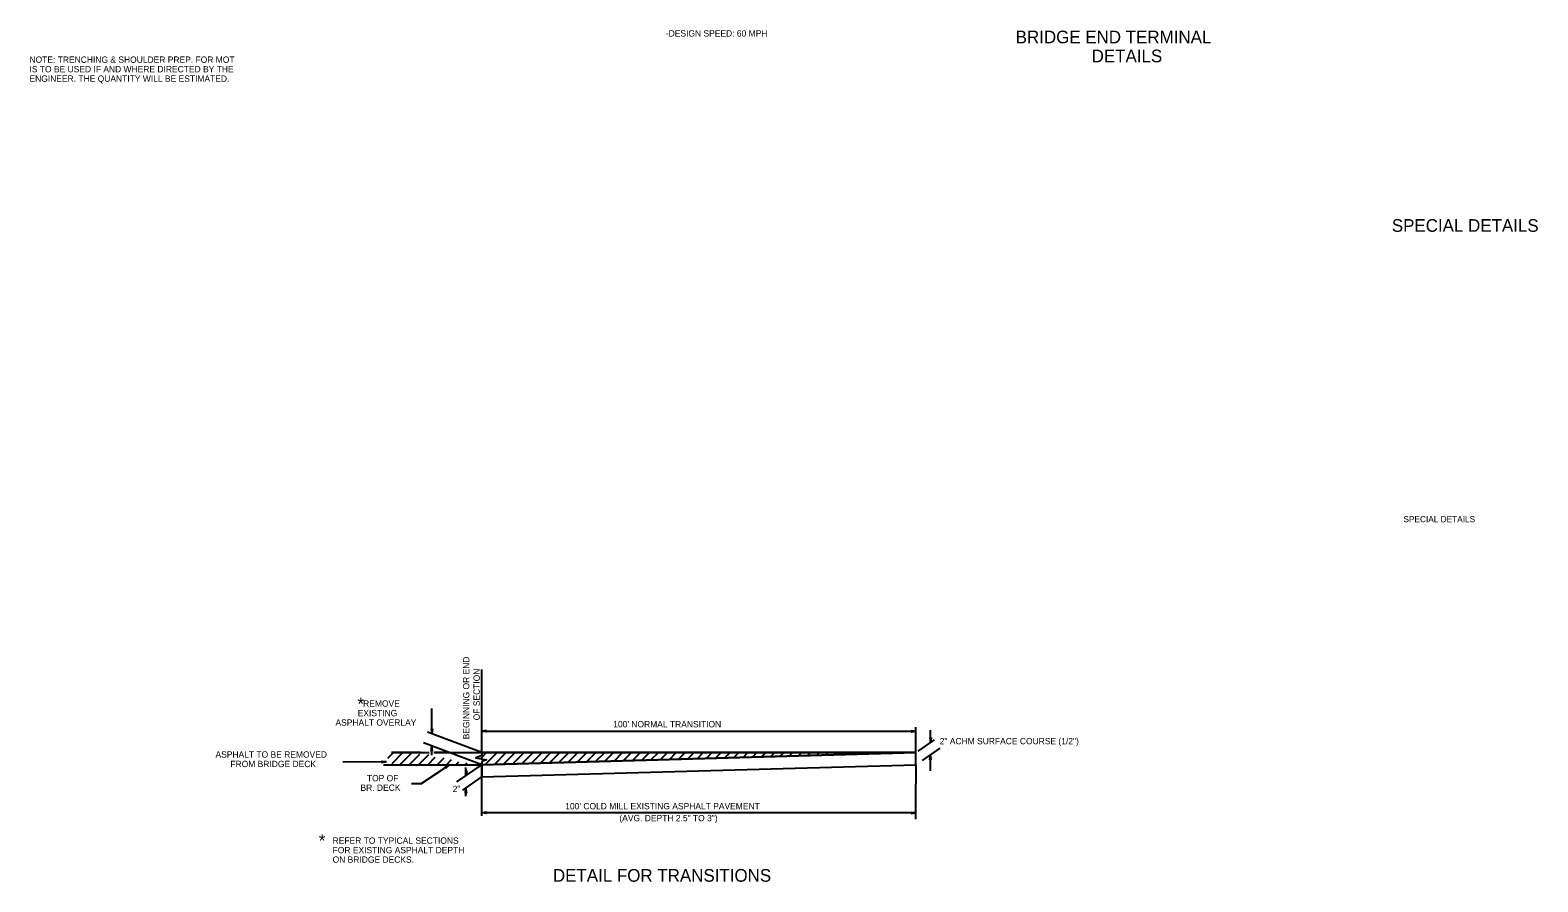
# Model space of a CAD drawing. Extents: x 1929624 to 1936506, y 596315 to 605721.
# Drawn here: x 1933916 to 1935345, y 602704 to 603512 of the extents above; entities that cross this region are included whole.
import ezdxf

# ---------------------------------------------------------------- set-up
doc = ezdxf.new("R2010")
doc.units = 0
for name, color, linetype in [('Default', 7, 'Continuous'), ('R_Border', 7, 'Continuous'), ('R_Border Prem', 7, 'Continuous')]:
    doc.layers.add(name, color=color, linetype=linetype)

msp = doc.modelspace()

# ---------------------------------------------------------------- linework, layer by layer
at = {"layer": 'Default'}
for p, q in [((1934343.8, 602827), (1934343.8, 602905.3)), ((1934296.4, 602844.5), (1934296.4, 602868.4)), ((1934343.8, 602826.5), (1934292.2, 602845.8)), ((1934295.7, 602848.9), (1934296.4, 602844.5)), ((1934295.7, 602848.9), (1934296.4, 602845.1)), ((1934297.1, 602848.9), (1934295.7, 602848.9)), ((1934296, 602848.9), (1934296.4, 602846)), ((1934296, 602848.9), (1934296.4, 602846.7)), ((1934296.2, 602848.9), (1934296.4, 602847.6)), ((1934296.2, 602848.9), (1934296.4, 602848.2)), ((1934297.1, 602848.9), (1934296.4, 602844.5)), ((1934296.6, 602848.9), (1934296.4, 602847.6)), ((1934296.8, 602848.9), (1934296.4, 602846)), ((1934296.8, 602848.9), (1934296.4, 602845.1)), ((1934296.6, 602848.9), (1934296.4, 602846.7)), ((1934296.4, 602848.9), (1934296.4, 602848.2)), ((1934348.4, 602847.4), (1934343.8, 602846.7)), ((1934343.8, 602846.7), (1934755.3, 602846.7)), ((1934348.4, 602846.1), (1934343.8, 602846.7)), ((1934348.4, 602847.2), (1934344.5, 602846.7)), ((1934348.4, 602846.1), (1934344.5, 602846.7)), ((1934348.4, 602847.2), (1934345.3, 602846.7)), ((1934348.4, 602846.3), (1934345.3, 602846.7)), ((1934348.4, 602847), (1934346.2, 602846.7)), ((1934348.4, 602846.3), (1934346.2, 602846.7)), ((1934348.4, 602847), (1934346.9, 602846.7)), ((1934348.4, 602846.5), (1934346.9, 602846.7)), ((1934348.4, 602846.7), (1934347.8, 602846.7)), ((1934348.4, 602846.5), (1934347.8, 602846.7)), ((1934348.4, 602846.1), (1934348.4, 602847.4)), ((1934750.7, 602847.4), (1934755.3, 602846.7)), ((1934750.7, 602847.4), (1934750.7, 602846.1)), ((1934750.7, 602847.2), (1934753.8, 602846.7)), ((1934750.7, 602847.2), (1934754.4, 602846.7)), ((1934750.7, 602847), (1934752.2, 602846.7)), ((1934750.7, 602847), (1934752.9, 602846.7)), ((1934750.7, 602846.1), (1934755.3, 602846.7)), ((1934750.7, 602846.5), (1934752.2, 602846.7)), ((1934750.7, 602846.3), (1934753.8, 602846.7)), ((1934750.7, 602846.1), (1934754.4, 602846.7)), ((1934750.7, 602846.3), (1934752.9, 602846.7)), ((1934750.7, 602846.5), (1934751.3, 602846.7)), ((1934750.7, 602846.7), (1934751.3, 602846.7)), ((1934755.3, 602826.5), (1934755.3, 602850.7)), ((1934769.1, 602836.1), (1934769.1, 602847.8)), ((1934343.8, 602815), (1934288.4, 602835.7)), ((1934295.7, 602828), (1934296.4, 602832.7)), ((1934295.7, 602828), (1934296.4, 602832)), ((1934296, 602828), (1934296.4, 602831.1)), ((1934296, 602828), (1934296.4, 602830.4)), ((1934296.2, 602828), (1934296.4, 602829.6)), ((1934296.2, 602828), (1934296.4, 602828.7)), ((1934297.1, 602828), (1934296.4, 602832.7)), ((1934296.4, 602824.2), (1934296.4, 602832.7)), ((1934296.8, 602828), (1934296.4, 602832)), ((1934296.8, 602828), (1934296.4, 602831.1)), ((1934296.6, 602828), (1934296.4, 602830.4)), ((1934296.6, 602828), (1934296.4, 602829.6)), ((1934296.4, 602828), (1934296.4, 602828.7)), ((1934757.4, 602828), (1934772.7, 602838.5)), ((1934761.5, 602819.1), (1934778.1, 602830.8)), ((1934768.4, 602840.7), (1934769.1, 602836.1)), ((1934769.8, 602840.7), (1934768.4, 602840.7)), ((1934768.7, 602840.7), (1934769.1, 602837.6)), ((1934768.7, 602840.7), (1934769.1, 602836.9)), ((1934768.9, 602840.7), (1934769.1, 602839.2)), ((1934768.9, 602840.7), (1934769.1, 602838.5)), ((1934769.8, 602840.7), (1934769.1, 602836.1)), ((1934769.3, 602840.7), (1934769.1, 602839.2)), ((1934769.6, 602840.7), (1934769.1, 602837.6)), ((1934769.8, 602840.7), (1934769.1, 602836.9)), ((1934769.6, 602840.7), (1934769.1, 602838.5)), ((1934769.1, 602840.7), (1934769.1, 602840.1)), ((1934769.3, 602840.7), (1934769.1, 602840.1)), ((1934212, 602817.7), (1934253.4, 602817.9)), ((1934248.7, 602817.1), (1934248.8, 602818.5)), ((1934248.7, 602818.2), (1934251.8, 602817.8)), ((1934248.7, 602817.1), (1934253.4, 602817.9)), ((1934248.8, 602818.5), (1934253.4, 602817.9)), ((1934248.8, 602818.1), (1934250.4, 602817.8)), ((1934248.8, 602818.1), (1934251, 602817.7)), ((1934248.8, 602817.4), (1934250.4, 602817.8)), ((1934248.8, 602817.8), (1934249.6, 602817.8)), ((1934248.8, 602817.8), (1934249.6, 602817.8)), ((1934248.8, 602817.4), (1934251, 602817.7)), ((1934248.9, 602818.4), (1934252.6, 602817.8)), ((1934248.9, 602817.3), (1934251.8, 602817.8)), ((1934248.9, 602817.3), (1934252.6, 602817.8)), ((1934250.5, 602815), (1934343.8, 602815)), ((1934254.8, 602821.2), (1934260, 602826.5)), ((1934258.3, 602826.5), (1934294, 602826.5)), ((1934258.7, 602816.3), (1934268.9, 602826.5)), ((1934266.7, 602815.5), (1934277.7, 602826.5)), ((1934275, 602815), (1934285, 602825)), ((1934283.9, 602815), (1934293.5, 602824.6)), ((1934286.1, 602796.9), (1934313.3, 602815)), ((1934292.7, 602815), (1934299.7, 602822)), ((1934295.7, 602828), (1934297.1, 602828)), ((1934298.2, 602826.5), (1934755.3, 602826.5)), ((1934301.5, 602815), (1934308, 602821.5)), ((1934309, 602813), (1934313.3, 602815)), ((1934309.2, 602812.9), (1934312.7, 602814.5)), ((1934309.8, 602811.8), (1934313.3, 602815)), ((1934309.9, 602812), (1934312.7, 602814.5)), ((1934310.4, 602815), (1934315.2, 602819.8)), ((1934319.2, 602815), (1934322, 602817.7)), ((1934320.2, 602798.7), (1934343.8, 602815)), ((1934328.1, 602815), (1934329.8, 602816.7)), ((1934336.9, 602815), (1934337.3, 602815.3)), ((1934342.8, 602820.8), (1934348.4, 602826.5)), ((1934343.8, 602815), (1934755.3, 602826.5)), ((1934343.8, 602766.4), (1934343.8, 602816.7)), ((1934343.8, 602803.4), (1934755.3, 602815)), ((1934355.7, 602815.3), (1934366.9, 602826.5)), ((1934755.3, 602815), (1934755.1, 602796.7)), ((1934755.3, 602815), (1934755.3, 602826.5)), ((1934768.5, 602819.6), (1934769.1, 602824.3)), ((1934768.5, 602819.6), (1934769.8, 602819.6)), ((1934768.7, 602819.6), (1934769.1, 602823.7)), ((1934768.7, 602819.6), (1934769.1, 602822.8)), ((1934768.9, 602819.6), (1934769.1, 602822.1)), ((1934768.9, 602819.6), (1934769.1, 602821.2)), ((1934769.1, 602809.2), (1934769.1, 602824.3)), ((1934769.8, 602819.6), (1934769.1, 602824.3)), ((1934769.8, 602819.6), (1934769.1, 602823.7)), ((1934769.6, 602819.6), (1934769.1, 602822.8)), ((1934769.6, 602819.6), (1934769.1, 602822.1)), ((1934769.3, 602819.6), (1934769.1, 602821.2)), ((1934769.3, 602819.6), (1934769.1, 602820.5)), ((1934769.1, 602819.6), (1934769.1, 602820.5)), ((1934309.8, 602811.8), (1934309, 602813)), ((1934309.2, 602812.7), (1934312, 602814)), ((1934309.4, 602812.6), (1934311.4, 602813.6)), ((1934309.4, 602812.6), (1934310.8, 602813.3)), ((1934309.5, 602812.4), (1934310.2, 602812.8)), ((1934309.5, 602812.4), (1934310.2, 602812.8)), ((1934309.7, 602812.1), (1934311.4, 602813.6)), ((1934309.7, 602812.1), (1934310.8, 602813.3)), ((1934309.9, 602812), (1934312, 602814)), ((1934325.8, 602790.8), (1934343.8, 602803.4)), ((1934328.2, 602809.3), (1934328.8, 602804.6)), ((1934329.5, 602809.3), (1934328.2, 602809.3)), ((1934328.4, 602809.3), (1934328.8, 602806.2)), ((1934328.4, 602809.3), (1934328.8, 602805.5)), ((1934328.6, 602809.3), (1934328.8, 602807.7)), ((1934328.6, 602809.3), (1934328.8, 602807.1)), ((1934328.8, 602804.6), (1934328.8, 602812.2)), ((1934329.5, 602809.3), (1934328.8, 602804.6)), ((1934329.1, 602809.3), (1934328.8, 602807.7)), ((1934329.3, 602809.3), (1934328.8, 602806.2)), ((1934329.5, 602809.3), (1934328.8, 602805.5)), ((1934329.3, 602809.3), (1934328.8, 602807.1)), ((1934328.8, 602809.3), (1934328.8, 602808.6)), ((1934329.1, 602809.3), (1934328.8, 602808.6)), ((1934286.1, 602796.9), (1934277.3, 602796.9)), ((1934328.2, 602788.1), (1934328.8, 602792.8)), ((1934328.2, 602788.1), (1934329.5, 602788.1)), ((1934328.4, 602788.1), (1934328.8, 602792.1)), ((1934328.4, 602788.1), (1934328.8, 602791.2)), ((1934328.6, 602788.1), (1934328.8, 602790.6)), ((1934328.6, 602788.1), (1934328.8, 602789.7)), ((1934329.5, 602788.1), (1934328.8, 602792.8)), ((1934328.8, 602785.3), (1934328.8, 602792.8)), ((1934329.5, 602788.1), (1934328.8, 602792.1)), ((1934329.3, 602788.1), (1934328.8, 602791.2)), ((1934329.3, 602788.1), (1934328.8, 602790.6)), ((1934329, 602788.1), (1934328.8, 602789.7)), ((1934329, 602788.1), (1934328.8, 602789)), ((1934328.8, 602788.1), (1934328.8, 602789)), ((1934755.1, 602763.2), (1934755.1, 602796.7)), ((1934348.2, 602769.9), (1934343.8, 602769.2)), ((1934755.1, 602769.2), (1934343.8, 602769.2)), ((1934348.2, 602768.6), (1934343.8, 602769.2)), ((1934348.2, 602769.9), (1934344.5, 602769.2)), ((1934348.2, 602768.8), (1934344.5, 602769.2)), ((1934348.2, 602769.7), (1934345.3, 602769.2)), ((1934348.2, 602768.8), (1934345.3, 602769.2)), ((1934348.2, 602769.7), (1934346, 602769.2)), ((1934348.2, 602769), (1934346, 602769.2)), ((1934348.2, 602769.4), (1934346.9, 602769.2)), ((1934348.2, 602769), (1934346.9, 602769.2)), ((1934348.2, 602769.4), (1934347.6, 602769.2)), ((1934348.2, 602769.2), (1934347.6, 602769.2)), ((1934348.2, 602768.6), (1934348.2, 602769.9)), ((1934750.7, 602769.9), (1934755.1, 602769.2)), ((1934750.7, 602769.9), (1934754.4, 602769.2)), ((1934750.7, 602769.9), (1934750.7, 602768.6)), ((1934750.7, 602769.7), (1934753.6, 602769.2)), ((1934750.7, 602769.7), (1934752.9, 602769.2)), ((1934750.7, 602769.4), (1934752, 602769.2)), ((1934750.7, 602769.4), (1934751.3, 602769.2)), ((1934750.7, 602768.6), (1934755.1, 602769.2)), ((1934750.7, 602769), (1934752, 602769.2)), ((1934750.7, 602768.8), (1934753.6, 602769.2)), ((1934750.7, 602768.8), (1934754.4, 602769.2)), ((1934750.7, 602769), (1934752.9, 602769.2)), ((1934750.7, 602769.2), (1934751.3, 602769.2))]:
    msp.add_line(p, q, dxfattribs=at)
for points in [[(1934285.6, 602826.5), (1934258.3, 602826.5)], [(1934343.8, 602815), (1934312.9, 602826.5), (1934299.2, 602826.5)], [(1934343.8, 602823.8), (1934338.1, 602821.6), (1934348.4, 602819.7), (1934343.8, 602818)], [(1934343.8, 602815), (1934343.8, 602803.4), (1934755.3, 602815), (1934755.3, 602826.5), (1934343.8, 602815)], [(1934343.8, 602815), (1934343.8, 602803.4), (1934755.3, 602815), (1934755.3, 602826.5), (1934343.8, 602815)]]:
    msp.add_lwpolyline(points, dxfattribs=at)
at = {"layer": 'R_Border'}
for p, q in [((1934347, 602815.1), (1934358.4, 602826.5)), ((1934364.4, 602815.6), (1934375.4, 602826.5)), ((1934373.2, 602815.8), (1934383.9, 602826.5)), ((1934381.9, 602816.1), (1934392.4, 602826.5)), ((1934390.6, 602816.3), (1934400.9, 602826.5)), ((1934399.4, 602816.5), (1934409.3, 602826.5)), ((1934408.1, 602816.8), (1934417.8, 602826.5)), ((1934416.8, 602817), (1934426.3, 602826.5)), ((1934425.6, 602817.3), (1934434.8, 602826.5)), ((1934434.3, 602817.5), (1934443.3, 602826.5)), ((1934443, 602817.8), (1934451.8, 602826.5)), ((1934451.7, 602818), (1934460.3, 602826.5)), ((1934460.5, 602818.3), (1934468.7, 602826.5)), ((1934469.2, 602818.5), (1934477.2, 602826.5)), ((1934477.9, 602818.7), (1934485.7, 602826.5)), ((1934486.7, 602819), (1934494.2, 602826.5)), ((1934495.4, 602819.2), (1934502.7, 602826.5)), ((1934504.1, 602819.5), (1934511.2, 602826.5)), ((1934512.9, 602819.7), (1934519.7, 602826.5)), ((1934521.6, 602820), (1934528.1, 602826.5)), ((1934530.3, 602820.2), (1934536.6, 602826.5)), ((1934539, 602820.5), (1934545.1, 602826.5)), ((1934547.8, 602820.7), (1934553.6, 602826.5)), ((1934556.5, 602820.9), (1934562.1, 602826.5)), ((1934565.2, 602821.2), (1934570.6, 602826.5)), ((1934574, 602821.4), (1934579.1, 602826.5)), ((1934582.7, 602821.7), (1934587.5, 602826.5)), ((1934591.4, 602821.9), (1934596, 602826.5)), ((1934600.2, 602822.2), (1934604.5, 602826.5)), ((1934608.9, 602822.4), (1934613, 602826.5)), ((1934617.6, 602822.7), (1934621.5, 602826.5)), ((1934626.3, 602822.9), (1934630, 602826.5)), ((1934635.1, 602823.1), (1934638.4, 602826.5)), ((1934643.8, 602823.4), (1934646.9, 602826.5)), ((1934652.5, 602823.6), (1934655.4, 602826.5)), ((1934661.3, 602823.9), (1934663.9, 602826.5)), ((1934670, 602824.1), (1934672.4, 602826.5)), ((1934678.7, 602824.4), (1934680.9, 602826.5)), ((1934687.5, 602824.6), (1934689.4, 602826.5)), ((1934696.2, 602824.9), (1934697.8, 602826.5)), ((1934704.9, 602825.1), (1934706.3, 602826.5)), ((1934713.6, 602825.3), (1934714.8, 602826.5)), ((1934722.4, 602825.6), (1934723.3, 602826.5)), ((1934731.1, 602825.8), (1934731.8, 602826.5)), ((1934739.8, 602826.1), (1934740.3, 602826.5)), ((1934748.6, 602826.3), (1934748.8, 602826.5))]:
    msp.add_line(p, q, dxfattribs=at)
for points in [[(1934343.8, 602818), (1934343.8, 602815), (1934755.3, 602826.5), (1934343.8, 602826.5)], [(1934343.8, 602826.5), (1934343.8, 602823.8)]]:
    msp.add_lwpolyline(points, dxfattribs=at)

# ---------------------------------------------------------------- texts
at = {"layer": 'Default'}
for s, height, rotation, p in [('    -DESIGN SPEED: 60 MPH', 6, 360, (1934509.3, 603505.7)), ('BRIDGE END TERMINAL', 12, 360, (1934849.8, 603499.3)), ('DETAILS', 12, 360, (1934921.8, 603481.3)), ('BEGINNING OR END', 6, 90, (1934332, 602839.1)), ('OF SECTION', 6, 90, (1934341.9, 602857.1)), (' REMOVE', 6, 360, (1934229.1, 602870)), ('ASPHALT OVERLAY', 6, 360, (1934205.1, 602852)), ('EXISTING ', 6, 360, (1934226.2, 602861)), ("100' NORMAL TRANSITION ", 6, 360, (1934468.4, 602850.4)), ('ASPHALT TO BE REMOVED', 6, 360, (1934091.4, 602821.7)), (' FROM BRIDGE DECK', 6, 360, (1934103.3, 602812.7)), ('TOP OF ', 6, 360, (1934234.9, 602799.2)), ('BR. DECK', 6, 360, (1934228.8, 602790.2)), ('2"', 6, 360, (1934316.2, 602789)), ("100' COLD MILL EXISTING ASPHALT PAVEMENT", 6, 360, (1934422.9, 602772.7)), ('(AVG. DEPTH 2.5" TO 3")', 6, 360, (1934474.2, 602761.4)), ('DETAIL FOR TRANSITIONS', 12, 360, (1934411.2, 602704))]:
    msp.add_text(s, height=height, rotation=rotation, dxfattribs=at).set_placement(p)
msp.add_text('2" ACHM SURFACE COURSE (1/2")', height=6, dxfattribs=at).set_placement((1934777.8, 602834.4))
at = {"layer": 'R_Border'}
for s, height, p in [('NOTE: TRENCHING & SHOULDER PREP. FOR MOT', 6, (1933915.1, 603480.8)), ('IS TO BE USED IF AND WHERE DIRECTED BY THE', 6, (1933915.1, 603471.8)), ('ENGINEER. THE QUANTITY WILL BE ESTIMATED.', 6, (1933915.1, 603462.8)), ('SPECIAL DETAILS', 12, (1935206.3, 603320.5)), ('*', 12, (1934225.9, 602866.7)), ('*', 12, (1934189.3, 602737)), ('REFER TO TYPICAL SECTIONS', 6, (1934202.4, 602740)), ('FOR EXISTING ASPHALT DEPTH ', 6, (1934202.4, 602731)), ('ON BRIDGE DECKS.', 6, (1934202.4, 602722))]:
    msp.add_text(s, height=height, rotation=360, dxfattribs=at).set_placement(p)
at = {"layer": 'R_Border Prem'}
msp.add_text('SPECIAL DETAILS', height=5.862, rotation=360, dxfattribs=at).set_placement((1935217.3, 603045))

doc.saveas('drawing.dxf')
